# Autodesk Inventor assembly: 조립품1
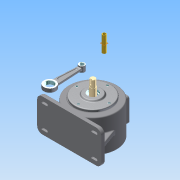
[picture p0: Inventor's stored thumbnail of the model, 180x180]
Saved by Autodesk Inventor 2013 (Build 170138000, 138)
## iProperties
Created: 2015-06
Part Number: 조립품1
Document SubType Name: Assembly
Designer: Administrator
Author: Administrator
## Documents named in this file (9)
- C:\Users\Administrator\Desktop\450606V1004\조립품1.iam
- C:\Users\Administrator\Desktop\450606V1004\본체.ipt
- C:\Users\Administrator\Desktop\450606V1004\메인 크랭크 축-구동부.ipt
- C:\Users\Administrator\Desktop\450606V1004\베어링 6204.ipt
- C:\Users\Administrator\Desktop\450606V1004\크랭크 서브축.ipt
- C:\Users\Administrator\Desktop\450606V1004\베어링 NA 4902.ipt
- C:\Users\Administrator\Desktop\450606V1004\메인커버.ipt
- C:\Users\Administrator\Desktop\450606V1004\피스톤 핀.ipt
- C:\Users\Administrator\Desktop\450606V1004\커넥팅 로드.ipt
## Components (1 placed, 1 different names)
1. 피스톤 핀:1
